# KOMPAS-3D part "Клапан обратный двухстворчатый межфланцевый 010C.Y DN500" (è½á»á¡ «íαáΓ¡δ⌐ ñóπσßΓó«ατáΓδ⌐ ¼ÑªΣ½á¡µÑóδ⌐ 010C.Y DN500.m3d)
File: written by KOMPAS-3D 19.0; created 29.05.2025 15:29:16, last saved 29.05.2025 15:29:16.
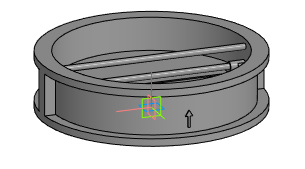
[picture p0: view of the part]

Document properties: Полное имя файла: E:\Dendor Работа Сачек\3D для проекитирвщиков\5.2 Тип 010C, 010C.Y Клапан обратный двухстворчатый межфланцевый\stp_Клапан обратный двухстворчатый межфланцевый 010C.Y\Клапан обратный двухстворчатый межфланцевый 010C.Y DN500.m3d

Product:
- Part/product: Клапан обратный двухстворчатый межфланцевый 010C.Y DN500

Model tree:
1. Операция без истории:1  (labels: Клапан обратный двухстворчатый межфланцевый 010C.Y DN500)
